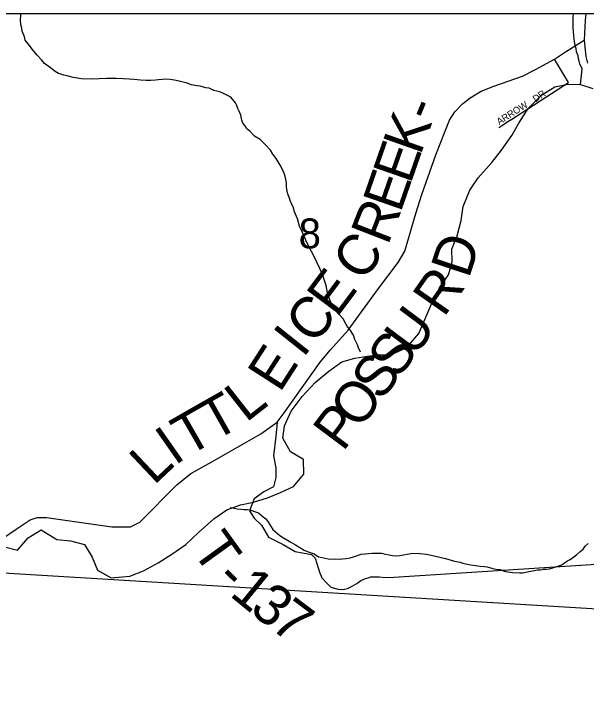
# Model space of a CAD drawing. Extents: x 1949938.81 to 1949945.61, y 152207.65 to 152214.09.
# Drawn here: x 1949940.583 to 1949941.382, y 152213.113 to 152214.087 of the extents above; entities that cross this region are included whole.
import ezdxf

# ---------------------------------------------------------------- set-up
doc = ezdxf.new("R2010")
doc.units = 0
for name, color, linetype in [('GM_X_County', 7, 'Continuous'), ('GM_X_County_Road', 7, 'Continuous'), ('GM_X_County_Road_Text', 7, 'Continuous'), ('GM_X_Minor_River', 7, 'Continuous'), ('GM_X_Section', 7, 'Continuous'), ('GM_X_Section_Text', 7, 'Continuous'), ('GM_X_State_Route', 7, 'Continuous'), ('GM_X_Township', 7, 'Continuous'), ('GM_X_Township_Road', 7, 'Continuous'), ('GM_X_Township_Road_Text', 7, 'Continuous'), ('GM_X_Township_ROW', 7, 'Continuous'), ('GM_X_Township_Subdivision', 7, 'Continuous'), ('GM_X_Township_Subdivision_Text', 7, 'Continuous')]:
    doc.layers.add(name, color=color, linetype=linetype)

msp = doc.modelspace()

# ---------------------------------------------------------------- linework, layer by layer
at = {"layer": 'GM_X_County'}
msp.add_lwpolyline([(1949945.60686, 152208.82659), (1949945.60686, 152214.0874), (1949938.80686, 152214.0874), (1949938.80686, 152213.18128)], dxfattribs=at)
at = {"layer": 'GM_X_County_Road'}
msp.add_lwpolyline([(1949940.56676, 152213.35433), (1949940.58626, 152213.36734), (1949940.60579, 152213.38035), (1949940.61554, 152213.3836), (1949940.62855, 152213.3836), (1949940.71964, 152213.37057), (1949940.74567, 152213.37057), (1949940.75868, 152213.37708), (1949940.81072, 152213.4291), (1949940.83025, 152213.44536), (1949940.85953, 152213.46162), (1949940.92784, 152213.50064), (1949940.95063, 152213.5169), (1949940.96038, 152213.52991), (1949941.0107, 152213.60068), (1949941.0254, 152213.61811), (1949941.0499, 152213.64533), (1949941.09237, 152213.70361), (1949941.1196, 152213.74011), (1949941.12885, 152213.7559), (1949941.14464, 152213.80872), (1949941.15281, 152213.83487), (1949941.17241, 152213.89042), (1949941.19168, 152213.9389), (1949941.19893, 152213.95077), (1949941.20947, 152213.96164), (1949941.22034, 152213.97021), (1949941.23583, 152213.97944), (1949941.25329, 152213.98636), (1949941.29349, 152214.00053), (1949941.31161, 152214.00976), (1949941.33838, 152214.02435), (1949941.35335, 152214.03454), (1949941.37982, 152214.05073)], dxfattribs=at)
at = {"layer": 'GM_X_Minor_River'}
for points in [[(1949940.59188, 152214.07854), (1949940.59237, 152214.08499), (1949940.5926, 152214.0874)], [(1949941.37431, 152213.98858), (1949941.37701, 152214.01057), (1949941.37372, 152214.01746), (1949941.37265, 152214.02128), (1949941.37195, 152214.0247), (1949941.37127, 152214.0289), (1949941.36909, 152214.03425), (1949941.36842, 152214.03919), (1949941.36698, 152214.0434), (1949941.36562, 152214.05215), (1949941.36532, 152214.05671), (1949941.36468, 152214.06318), (1949941.36438, 152214.06774), (1949941.36411, 152214.0742), (1949941.36427, 152214.08293), (1949941.36463, 152214.0874)], [(1949941.06701, 152213.61484), (1949941.06446, 152213.62058), (1949941.06303, 152213.62516), (1949941.05937, 152213.63243), (1949941.0572, 152213.63854), (1949941.05242, 152213.6466), (1949941.04908, 152213.65007), (1949941.0454, 152213.65659), (1949941.0432, 152213.6608), (1949941.03689, 152213.66775), (1949941.03096, 152213.67544), (1949941.02617, 152213.68273), (1949941.02256, 152213.69305), (1949941.02113, 152213.69763), (1949941.01904, 152213.70792), (1949941.01759, 152213.71212), (1949941.01473, 152213.72166), (1949941.01036, 152213.73161), (1949941.00561, 152213.74156), (1949941.00086, 152213.75113), (1949940.99573, 152213.76071), (1949940.9906, 152213.77105), (1949940.98587, 152213.78176), (1949940.98186, 152213.79094), (1949940.97901, 152213.80086), (1949940.97502, 152213.8108), (1949940.97324, 152213.81767), (1949940.97141, 152213.82112), (1949940.96885, 152213.82648), (1949940.96778, 152213.82991), (1949940.96597, 152213.8345), (1949940.96491, 152213.83907), (1949940.96389, 152213.84554), (1949940.96361, 152213.85124), (1949940.96294, 152213.85619), (1949940.96188, 152213.86077), (1949940.95898, 152213.86803), (1949940.95496, 152213.87607), (1949940.94944, 152213.88528), (1949940.94462, 152213.89144), (1949940.94131, 152213.89681), (1949940.93463, 152213.90452), (1949940.9268, 152213.91186), (1949940.91893, 152213.91655), (1949940.91299, 152213.92311), (1949940.9085, 152213.9266), (1949940.90593, 152213.9312), (1949940.90296, 152213.93467), (1949940.90152, 152213.93887), (1949940.89975, 152213.94573), (1949940.89758, 152213.95147), (1949940.89575, 152213.9553), (1949940.89431, 152213.9595), (1949940.89248, 152213.96295), (1949940.8858, 152213.97103), (1949940.87492, 152213.97691), (1949940.8704, 152213.97851), (1949940.86211, 152213.98055), (1949940.85572, 152213.98369), (1949940.85119, 152213.98415), (1949940.8429, 152213.98657), (1949940.83836, 152213.98702), (1949940.8308, 152213.98829), (1949940.82479, 152213.99067), (1949940.81574, 152213.99311), (1949940.8097, 152213.99435), (1949940.80101, 152213.99563), (1949940.7961, 152213.9961), (1949940.7851, 152213.99552), (1949940.78092, 152213.99484), (1949940.7741, 152213.99457), (1949940.76766, 152213.9943), (1949940.75971, 152213.99482), (1949940.75026, 152213.99573), (1949940.74383, 152213.99622), (1949940.73551, 152213.99674), (1949940.72567, 152213.99729), (1949940.71544, 152213.99709), (1949940.71203, 152213.99714), (1949940.7018, 152213.99694), (1949940.69118, 152213.99636), (1949940.67679, 152213.9966), (1949940.66886, 152213.99788), (1949940.66547, 152213.9987), (1949940.65717, 152214.00073), (1949940.65265, 152214.00195), (1949940.6485, 152214.00316), (1949940.64511, 152214.00436), (1949940.64062, 152214.00709), (1949940.63389, 152214.01214), (1949940.62566, 152214.01798), (1949940.62121, 152214.02337), (1949940.61526, 152214.02992), (1949940.60896, 152214.03762), (1949940.60304, 152214.0457), (1949940.59858, 152214.05071), (1949940.59753, 152214.05529), (1949940.59426, 152214.06332), (1949940.59396, 152214.0675), (1949940.59253, 152214.07284), (1949940.59188, 152214.07854)], [(1949940.95872, 152213.49436), (1949940.96106, 152213.51182), (1949940.97023, 152213.53228), (1949940.98547, 152213.55272), (1949941.00373, 152213.57239), (1949941.02273, 152213.58826), (1949941.04096, 152213.6011), (1949941.05916, 152213.60635), (1949941.08947, 152213.61079), (1949941.11068, 152213.61148), (1949941.13193, 152213.62127), (1949941.14867, 152213.64095), (1949941.15861, 152213.66368), (1949941.16703, 152213.68339), (1949941.17772, 152213.70461), (1949941.18991, 152213.72278), (1949941.19529, 152213.74098), (1949941.19461, 152213.75844), (1949941.20226, 152213.77739), (1949941.20765, 152213.79863), (1949941.21076, 152213.81835), (1949941.21995, 152213.84109), (1949941.23138, 152213.85851), (1949941.25041, 152213.8797), (1949941.26411, 152213.89711), (1949941.27859, 152213.91756), (1949941.28851, 152213.93498), (1949941.30147, 152213.95543), (1949941.32048, 152213.97434), (1949941.3387, 152213.98566), (1949941.3569, 152213.9894), (1949941.37431, 152213.98858), (1949941.39171, 152213.9832)], [(1949940.56955, 152213.34245), (1949940.58771, 152213.33783), (1949940.60293, 152213.35523), (1949940.62115, 152213.36655), (1949940.64306, 152213.35281), (1949940.66199, 152213.35122), (1949940.68166, 152213.34583), (1949940.69218, 152213.32834), (1949940.69968, 152213.31009), (1949940.71857, 152213.29939), (1949940.74509, 152213.30157), (1949940.76405, 152213.30909), (1949940.78455, 152213.32041), (1949940.80353, 152213.33248), (1949940.82328, 152213.34607), (1949940.84077, 152213.36271), (1949940.86206, 152213.38161), (1949940.88029, 152213.39445), (1949940.89925, 152213.40121), (1949940.91744, 152213.40494), (1949940.93716, 152213.41094), (1949940.95537, 152213.41847), (1949940.97358, 152213.42675), (1949940.98804, 152213.44416), (1949940.98737, 152213.46466), (1949940.96924, 152213.47535), (1949940.95872, 152213.49436)], [(1949940.88516, 152213.39769), (1949940.88856, 152213.39725), (1949940.89498, 152213.39562), (1949940.89989, 152213.39516), (1949940.90443, 152213.39471), (1949940.90897, 152213.39463), (1949940.91388, 152213.39379), (1949940.92066, 152213.39177), (1949940.9248, 152213.39018), (1949940.93114, 152213.38438), (1949940.93488, 152213.38166), (1949940.93747, 152213.3782), (1949940.94485, 152213.36706), (1949940.95455, 152213.35854), (1949940.95942, 152213.35542), (1949940.96991, 152213.34917), (1949940.97628, 152213.34526), (1949940.98865, 152213.33784), (1949940.99392, 152213.33585), (1949941.0022, 152213.33267), (1949941.00856, 152213.32877), (1949941.01347, 152213.32755), (1949941.02215, 152213.32588), (1949941.02555, 152213.32544), (1949941.03237, 152213.32571), (1949941.0373, 152213.32562), (1949941.04678, 152213.32622), (1949941.05285, 152213.32726), (1949941.05743, 152213.3287), (1949941.06809, 152213.33231), (1949941.07379, 152213.33298), (1949941.08365, 152213.33357), (1949941.08706, 152213.33389), (1949941.09653, 152213.33373), (1949941.10219, 152213.3325), (1949941.10709, 152213.33127), (1949941.11162, 152213.33044), (1949941.11767, 152213.32996), (1949941.12223, 152213.33064), (1949941.13211, 152213.33237), (1949941.14009, 152213.33375), (1949941.14993, 152213.33321), (1949941.159, 152213.33229), (1949941.1658, 152213.33104), (1949941.17975, 152213.32777), (1949941.18579, 152213.32615), (1949941.1986, 152213.32251), (1949941.20653, 152213.32124), (1949941.2103, 152213.32004), (1949941.21633, 152213.31841), (1949941.22124, 152213.31757), (1949941.23447, 152213.31583), (1949941.23975, 152213.31498), (1949941.24391, 152213.31453), (1949941.25221, 152213.31249), (1949941.25636, 152213.31166), (1949941.26203, 152213.31081), (1949941.26994, 152213.3084), (1949941.27938, 152213.30672), (1949941.2896, 152213.30616), (1949941.29338, 152213.3061), (1949941.30251, 152213.30823), (1949941.31011, 152213.30962), (1949941.31429, 152213.3103), (1949941.31846, 152213.31062), (1949941.32302, 152213.3113), (1949941.3268, 152213.31123), (1949941.33136, 152213.31191), (1949941.33745, 152213.31371), (1949941.34279, 152213.31552), (1949941.34851, 152213.3177), (1949941.35196, 152213.3203), (1949941.35656, 152213.32326), (1949941.36, 152213.3251), (1949941.36499, 152213.32844), (1949941.3696, 152213.33215), (1949941.37345, 152213.33589), (1949941.37806, 152213.33961), (1949941.38116, 152213.34373), (1949941.38502, 152213.34746)]]:
    msp.add_lwpolyline(points, dxfattribs=at)
at = {"layer": 'GM_X_Section'}
msp.add_line((1949941.56081, 152214.0874), (1949940.48088, 152214.0874), dxfattribs=at)
msp.add_lwpolyline([(1949940.48088, 152214.0874), (1949940.4294, 152213.31462), (1949941.51331, 152213.24912), (1949941.56081, 152214.0874)], dxfattribs=at)
msp.add_lwpolyline([(1949941.51331, 152213.24912), (1949941.4524, 152212.22316), (1949940.36091, 152212.28639), (1949940.4294, 152213.31462)], close=True, dxfattribs=at)
at = {"layer": 'GM_X_State_Route'}
msp.add_lwpolyline([(1949941.38197, 152214.0874), (1949941.38106, 152214.07857), (1949941.37982, 152214.05073), (1949941.38176, 152214.02801), (1949941.38432, 152214.01846)], dxfattribs=at)
at = {"layer": 'GM_X_Township'}
msp.add_lwpolyline([(1949942.68389, 152214.0874), (1949938.80686, 152214.0874), (1949938.80686, 152213.18128)], dxfattribs=at)
at = {"layer": 'GM_X_Township_Road'}
msp.add_lwpolyline([(1949940.95063, 152213.5169), (1949940.94882, 152213.49674), (1949940.94547, 152213.46993), (1949940.94882, 152213.45318), (1949940.94882, 152213.43977), (1949940.94547, 152213.42637), (1949940.93206, 152213.41967), (1949940.91865, 152213.40962), (1949940.91195, 152213.39286), (1949940.91865, 152213.38281), (1949940.92871, 152213.37276), (1949940.93876, 152213.356), (1949940.95888, 152213.34595), (1949940.97564, 152213.33591), (1949940.99865, 152213.33193), (1949941.00376, 152213.32681), (1949941.00615, 152213.31949), (1949941.00972, 152213.30722), (1949941.01313, 152213.29921), (1949941.01926, 152213.29257), (1949941.02591, 152213.2861), (1949941.03579, 152213.28337)], dxfattribs=at)
at = {"layer": 'GM_X_Township_ROW'}
msp.add_lwpolyline([(1949941.03579, 152213.28337), (1949941.04227, 152213.28303), (1949941.04891, 152213.28422), (1949941.05538, 152213.28763), (1949941.06203, 152213.29121), (1949941.06748, 152213.29547), (1949941.07396, 152213.29819), (1949941.0777, 152213.29939), (1949941.08179, 152213.30058), (1949941.08605, 152213.30092), (1949941.09321, 152213.30092), (1949941.10224, 152213.29973), (1949941.11382, 152213.30006), (1949941.41138, 152213.31917), (1949941.42814, 152213.32252), (1949941.4382, 152213.31582), (1949941.44137, 152213.31582)], dxfattribs=at)
at = {"layer": 'GM_X_Township_Subdivision'}
for points in [[(1949941.27658, 152213.93936), (1949941.27699, 152213.93963), (1949941.35765, 152213.99156), (1949941.33838, 152214.02435)], [(1949941.26049, 152213.92886), (1949941.27658, 152213.93936)]]:
    msp.add_lwpolyline(points, dxfattribs=at)

# ---------------------------------------------------------------- texts
at = {"layer": 'GM_X_County_Road_Text'}
for s, rotation, p in [('-', 67.36362, (1949941.16725, 152213.93485)), ('K', 70.51672, (1949941.15087, 152213.88849)), ('E', 70.77188, (1949941.13689, 152213.84842)), ('E', 70.8018, (1949941.12292, 152213.80829)), ('R', 68.7527, (1949941.10524, 152213.76272)), ('C', 54.13022, (1949941.07035, 152213.71103)), ('D', 71.63292, (1949941.21825, 152213.71631)), ('E', 53.22908, (1949941.03403, 152213.66205)), ('R', 55.10869, (1949941.18356, 152213.66209)), ('C', 49.24355, (1949941.00086, 152213.62333)), ('U', 53.15474, (1949941.14193, 152213.6063)), ('I', 51.5328, (1949940.98673, 152213.60553)), ('S', 53.05494, (1949941.11882, 152213.57557)), ('E', 57.22295, (1949940.95432, 152213.55684)), ('S', 53.03115, (1949941.09575, 152213.54493)), ('O', 53.03493, (1949941.06569, 152213.50498)), ('L', 38.16735, (1949940.90708, 152213.51538)), ('T', 29.49105, (1949940.86229, 152213.48923)), ('T', 29.91032, (1949940.82554, 152213.46809)), ('P', 53.03566, (1949941.04264, 152213.47435)), ('I', 34.99298, (1949940.80755, 152213.45543)), ('L', 43.31828, (1949940.77832, 152213.42765))]:
    msp.add_text(s, height=0.05682, rotation=rotation, dxfattribs=at).set_placement(p)
at = {"layer": 'GM_X_Section_Text'}
msp.add_text('8', height=0.04186, rotation=0.00001, dxfattribs=at).set_placement((1949940.98071, 152213.75969))
at = {"layer": 'GM_X_Township_Road_Text'}
for s, rotation, p in [('T', 305.80808, (1949940.83022, 152213.33781)), ('-', 315.31718, (1949940.86177, 152213.29554)), ('1', 320.74153, (1949940.88272, 152213.27521)), ('3', 321.35179, (1949940.91033, 152213.25264)), ('7', 323.04152, (1949940.93911, 152213.22967))]:
    msp.add_text(s, height=0.05682, rotation=rotation, dxfattribs=at).set_placement(p)
at = {"layer": 'GM_X_Township_Subdivision_Text'}
for s, rotation, p in [('DR', 34.50968, (1949941.31179, 152213.96359)), ('ARROW', 32.46958, (1949941.261, 152213.93196))]:
    msp.add_text(s, height=0.00947, rotation=rotation, dxfattribs=at).set_placement(p)

doc.saveas('drawing.dxf')
